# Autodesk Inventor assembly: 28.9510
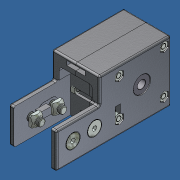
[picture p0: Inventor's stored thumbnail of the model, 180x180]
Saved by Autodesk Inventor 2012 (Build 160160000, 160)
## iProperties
Created: 2007-06
Part Number: 28.9510
Document SubType Name: Assembly
Designer: Andy Moles
Description: MACHINE TO 28.9510/1 & 28.9510/2
Mass: 933.458 g
Surface Area: 1145.68 cm^2
Volume: 290.933 cm^3
Density: 3.2085 g/cm^3
Author: Andy Moles
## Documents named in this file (12)
- C:\Andys Backup Data\ANDY'S INVENTOR\INVENTOR LIBRARIES\PARTS LIBRARY\READY FOR USE MODULES LR\28.9510 TIMING BELT PULLEY LR 6  .375.iam
- C:\Andys Backup Data\ANDY'S INVENTOR\INVENTOR LIBRARIES\PARTS LIBRARY\FASTENING ELEMENTS\SET SCREWS\SET SCREW M6X25 FLAT POINT DIN 913.ipt
- C:\Andys Backup Data\ANDY'S INVENTOR\INVENTOR LIBRARIES\PARTS LIBRARY\FASTENING ELEMENTS\NUTS\21.1525 M6 HEX NUT.ipt
- C:\Andys Backup Data\ANDY'S INVENTOR\INVENTOR LIBRARIES\PARTS LIBRARY\READY FOR USE MODULES LR\SUBCOMPONENTS\50.0805 42X20X8 BALL BEARING 16004Z.ipt
- C:\Andys Backup Data\ANDY'S INVENTOR\INVENTOR LIBRARIES\PARTS LIBRARY\READY FOR USE MODULES LR\SUBCOMPONENTS\28.0510 TIMING BELT PULLEY LR6 RIGHT PLATE.ipt
- C:\Andys Backup Data\ANDY'S INVENTOR\INVENTOR LIBRARIES\PARTS LIBRARY\FASTENING ELEMENTS\SCREWS CAP\21.1171 M6X50.ipt
- C:\Andys Backup Data\ANDY'S INVENTOR\INVENTOR LIBRARIES\PARTS LIBRARY\FASTENING ELEMENTS\SCREWS COUNTERSUNK\21.1514 M8X20 CSUNK.IPT
- C:\Andys Backup Data\ANDY'S INVENTOR\INVENTOR LIBRARIES\PARTS LIBRARY\FASTENING ELEMENTS\SUBCOMPONENTS\21.1386 SCREW CON ANTI ROT.ipt
- C:\Andys Backup Data\ANDY'S INVENTOR\INVENTOR LIBRARIES\PARTS LIBRARY\FASTENING ELEMENTS\NUTS\21.1351 M8 SQUARE NUT.ipt
- C:\Andys Backup Data\ANDY'S INVENTOR\INVENTOR LIBRARIES\PARTS LIBRARY\READY FOR USE MODULES LR\SUBCOMPONENTS\28.9510_2 LR6 LEFT SET SCREW ACCESS.ipt
- C:\Andys Backup Data\ANDY'S INVENTOR\INVENTOR LIBRARIES\PARTS LIBRARY\READY FOR USE MODULES LR\SUBCOMPONENTS\28.9510_1 TIMING BELT PULLEY LR6 PULLEY  .375in.ipt
- C:\Andys Backup Data\ANDY'S INVENTOR\INVENTOR LIBRARIES\PARTS LIBRARY\FASTENING ELEMENTS\SET SCREWS\21.9851_1 M5X5 SET SCREW THREAD LOCK SS.iam
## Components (28 placed, 11 different names)
1. 28.9510_2 LR6 LEFT SET SCREW ACCESS:1 — Flush:1, Mate:1, Flush:2, Mate:2, Flush:3, Insert:1, Mate:5, Mate:7, Flush:4, Flush:5, Insert:3, Insert:4, Insert:5, Insert:6, Insert:11, Insert:12, Insert:16, Mate:12, Insert:20, Angle:5
2. SET SCREW M6X25 FLAT POINT DIN 913:1 — Mate:2, Flush:3
3. 21.1525 M6 HEX NUT:1
4. 28.0510 42X20X8 BALL BEARING 16004Z:1 — Insert:1
5. 28.0510 42X20X8 BALL BEARING 16004Z:2 — Insert:21
6. 28.9510_1 TIMING BELT PULLEY LR6 PULLEY  .375in:1 — Mate:5, Mate:6, Mate:13, Mate:14
7. 28.0510 TIMING BELT PULLEY LR6 RIGHT PLATE:1 — Mate:7, Flush:4, Flush:5, Mate:8, Flush:6, Insert:13, Insert:14, Insert:15, Mate:11, Insert:18, Insert:21, Insert:22, Insert:23, Insert:24, Insert:25, Angle:1, Angle:2, Angle:3, Angle:4
8. SET SCREW M6X25 FLAT POINT DIN 913:2 — Mate:8, Flush:6
9. 21.1525 M6 HEX NUT:2
10. 21.1171 M6X50:1 — Insert:3
11. 21.1171 M6X50:2 — Insert:4
12. 21.1171 M6X50:3 — Insert:5
13. 21.1171 M6X50:4 — Insert:6
14. 21.1525 M6 HEX NUT:3 — Insert:23, Angle:4
15. 21.1525 M6 HEX NUT:4 — Insert:22, Angle:1
16. 21.1525 M6 HEX NUT:5 — Insert:24, Angle:3
17. 21.1525 M6 HEX NUT:6 — Insert:25, Angle:2
18. 21.1514 M8x20 C'SUNK:1 — Insert:11
19. 21.1514 M8x20 C'SUNK:2 — Insert:12
20. 21.1514 M8x20 C'SUNK:3 — Insert:14
21. 21.1514 M8x20 C'SUNK:4 — Insert:13
22. 21.1386 SCREW CON ANTI ROT:1 — Insert:15, Mate:11, Insert:17
23. 21.1386 SCREW CON ANTI ROT:2 — Insert:16, Mate:12, Insert:19
24. 21.1351 M8 SQUARE NUT:1 — Insert:17
25. 21.1351 M8 SQUARE NUT:2 — Insert:18
26. 21.1351 M8 SQUARE NUT:3 — Insert:19
27. 21.1351 M8 SQUARE NUT:4 — Insert:20
28. 21.9851_1 M5X5 SET SCREW THREAD LOCK SS:1 [sub-assembly] — Mate:13, Mate:14, Angle:5
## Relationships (41: Insert 20, Mate 10, Flush 6, Angle 5)
- Flush:1: 28.9510_2 LR6 LEFT SET SCREW ACCESS:1
- Mate:1: 28.9510_2 LR6 LEFT SET SCREW ACCESS:1
- Flush:2: 28.9510_2 LR6 LEFT SET SCREW ACCESS:1
- Mate:2: 28.9510_2 LR6 LEFT SET SCREW ACCESS:1 ↔ SET SCREW M6X25 FLAT POINT DIN 913:1
- Flush:3: 28.9510_2 LR6 LEFT SET SCREW ACCESS:1 ↔ SET SCREW M6X25 FLAT POINT DIN 913:1
- Insert:1: 28.9510_2 LR6 LEFT SET SCREW ACCESS:1 ↔ 28.0510 42X20X8 BALL BEARING 16004Z:1
- Mate:5: 28.9510_2 LR6 LEFT SET SCREW ACCESS:1 ↔ 28.9510_1 TIMING BELT PULLEY LR6 PULLEY  .375in:1
- Mate:6: 28.9510_1 TIMING BELT PULLEY LR6 PULLEY  .375in:1
- Mate:7: 28.9510_2 LR6 LEFT SET SCREW ACCESS:1 ↔ 28.0510 TIMING BELT PULLEY LR6 RIGHT PLATE:1
- Flush:4: 28.9510_2 LR6 LEFT SET SCREW ACCESS:1 ↔ 28.0510 TIMING BELT PULLEY LR6 RIGHT PLATE:1
- Flush:5: 28.9510_2 LR6 LEFT SET SCREW ACCESS:1 ↔ 28.0510 TIMING BELT PULLEY LR6 RIGHT PLATE:1
- Mate:8: 28.0510 TIMING BELT PULLEY LR6 RIGHT PLATE:1 ↔ SET SCREW M6X25 FLAT POINT DIN 913:2
- Flush:6: 28.0510 TIMING BELT PULLEY LR6 RIGHT PLATE:1 ↔ SET SCREW M6X25 FLAT POINT DIN 913:2
- Insert:3: 28.9510_2 LR6 LEFT SET SCREW ACCESS:1 ↔ 21.1171 M6X50:1
- Insert:4: 28.9510_2 LR6 LEFT SET SCREW ACCESS:1 ↔ 21.1171 M6X50:2
- Insert:5: 28.9510_2 LR6 LEFT SET SCREW ACCESS:1 ↔ 21.1171 M6X50:3
- Insert:6: 28.9510_2 LR6 LEFT SET SCREW ACCESS:1 ↔ 21.1171 M6X50:4
- Insert:11: 28.9510_2 LR6 LEFT SET SCREW ACCESS:1 ↔ 21.1514 M8x20 C'SUNK:1
- Insert:12: 28.9510_2 LR6 LEFT SET SCREW ACCESS:1 ↔ 21.1514 M8x20 C'SUNK:2
- Insert:13: 28.0510 TIMING BELT PULLEY LR6 RIGHT PLATE:1 ↔ 21.1514 M8x20 C'SUNK:4
- Insert:14: 28.0510 TIMING BELT PULLEY LR6 RIGHT PLATE:1 ↔ 21.1514 M8x20 C'SUNK:3
- Insert:15: 28.0510 TIMING BELT PULLEY LR6 RIGHT PLATE:1 ↔ 21.1386 SCREW CON ANTI ROT:1
- Mate:11: 28.0510 TIMING BELT PULLEY LR6 RIGHT PLATE:1 ↔ 21.1386 SCREW CON ANTI ROT:1
- Insert:16: 28.9510_2 LR6 LEFT SET SCREW ACCESS:1 ↔ 21.1386 SCREW CON ANTI ROT:2
- Mate:12: 28.9510_2 LR6 LEFT SET SCREW ACCESS:1 ↔ 21.1386 SCREW CON ANTI ROT:2
- Insert:17: 21.1386 SCREW CON ANTI ROT:1 ↔ 21.1351 M8 SQUARE NUT:1
- Insert:18: 28.0510 TIMING BELT PULLEY LR6 RIGHT PLATE:1 ↔ 21.1351 M8 SQUARE NUT:2
- Insert:19: 21.1386 SCREW CON ANTI ROT:2 ↔ 21.1351 M8 SQUARE NUT:3
- Insert:20: 28.9510_2 LR6 LEFT SET SCREW ACCESS:1 ↔ 21.1351 M8 SQUARE NUT:4
- Insert:21: 28.0510 42X20X8 BALL BEARING 16004Z:2 ↔ 28.0510 TIMING BELT PULLEY LR6 RIGHT PLATE:1
- Insert:22: 28.0510 TIMING BELT PULLEY LR6 RIGHT PLATE:1 ↔ 21.1525 M6 HEX NUT:4
- Insert:23: 28.0510 TIMING BELT PULLEY LR6 RIGHT PLATE:1 ↔ 21.1525 M6 HEX NUT:3
- Insert:24: 28.0510 TIMING BELT PULLEY LR6 RIGHT PLATE:1 ↔ 21.1525 M6 HEX NUT:5
- Insert:25: 28.0510 TIMING BELT PULLEY LR6 RIGHT PLATE:1 ↔ 21.1525 M6 HEX NUT:6
- Angle:1: 28.0510 TIMING BELT PULLEY LR6 RIGHT PLATE:1 ↔ 21.1525 M6 HEX NUT:4
- Angle:2: 28.0510 TIMING BELT PULLEY LR6 RIGHT PLATE:1 ↔ 21.1525 M6 HEX NUT:6
- Angle:3: 28.0510 TIMING BELT PULLEY LR6 RIGHT PLATE:1 ↔ 21.1525 M6 HEX NUT:5
- Angle:4: 28.0510 TIMING BELT PULLEY LR6 RIGHT PLATE:1 ↔ 21.1525 M6 HEX NUT:3
- Mate:13: 28.9510_1 TIMING BELT PULLEY LR6 PULLEY  .375in:1 ↔ 21.9851_1 M5X5 SET SCREW THREAD LOCK SS:1
- Mate:14: 28.9510_1 TIMING BELT PULLEY LR6 PULLEY  .375in:1 ↔ 21.9851_1 M5X5 SET SCREW THREAD LOCK SS:1
- Angle:5: 28.9510_2 LR6 LEFT SET SCREW ACCESS:1 ↔ 21.9851_1 M5X5 SET SCREW THREAD LOCK SS:1
